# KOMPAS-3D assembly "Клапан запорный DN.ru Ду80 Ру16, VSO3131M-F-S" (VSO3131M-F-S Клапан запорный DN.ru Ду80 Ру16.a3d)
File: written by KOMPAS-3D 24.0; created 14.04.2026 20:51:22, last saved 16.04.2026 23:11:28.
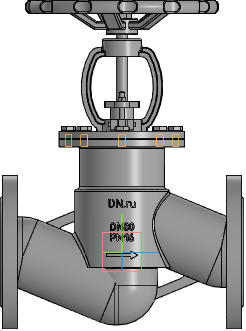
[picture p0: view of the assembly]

Document properties: Автор: R2D2; Полное имя файла: E:\Работа\Зайцев\VSO3131M-F-S Клапан запорный DN.ru Ду15-100 Ру16\DN80\исходные материалы\VSO3131M-F-S Клапан запорный DN.ru Ду80 Ру16.a3d

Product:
- Component [detail]: Корпус  | qty 1  | pos. 1  | Масса: 6.9; Автор: R2D2; source file: Корпус.m3d
- Component [detail]: Клапан запорный DN.ru Ду80 Ру16  | designation VSO1121M-F-S  | qty 1  | pos. 2  | Масса: 28.77; Раздел спецификации: Прочие изделия; Примечание: D090-01949; Автор: R2D2; source file: 2.m3d
- Part/product: Клапан запорный DN.ru Ду80 Ру16  | designation VSO3131M-F-S
    Масса: 20.25
    Раздел спецификации: Прочие изделия
    Примечание: D090-02953

Referenced files in E:\Работа\Зайцев\VSO3131M-F-S Клапан запорный DN.ru Ду15-100 Ру16\DN80\исходные материалы\: Корпус.m3d, 2.m3d
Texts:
  VSO3131M-F-S
  VSO1121M-F-S Клапан запорный DN.ru Ду80 Ру16
  Плоскость ZY.Начало координат
  Ось Y.Начало координат
  Плоскость ZX.Начало координат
